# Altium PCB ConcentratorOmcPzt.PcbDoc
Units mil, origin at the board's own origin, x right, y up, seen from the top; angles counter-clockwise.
Board outline 15500 x 6000 mil, 2 copper layers (Top Layer, Bottom Layer); 22 components, 67 nets, 387 pads, 49 vias.
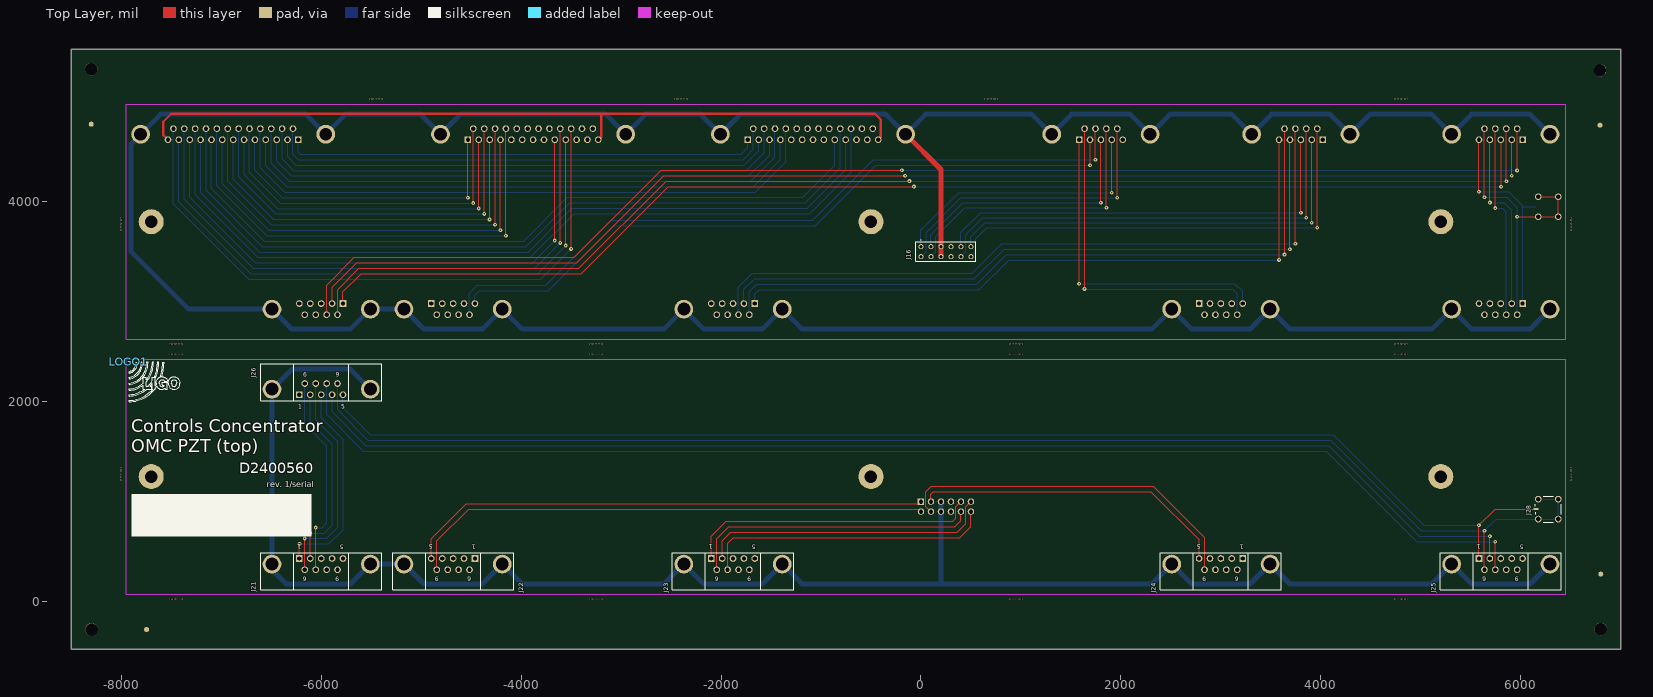
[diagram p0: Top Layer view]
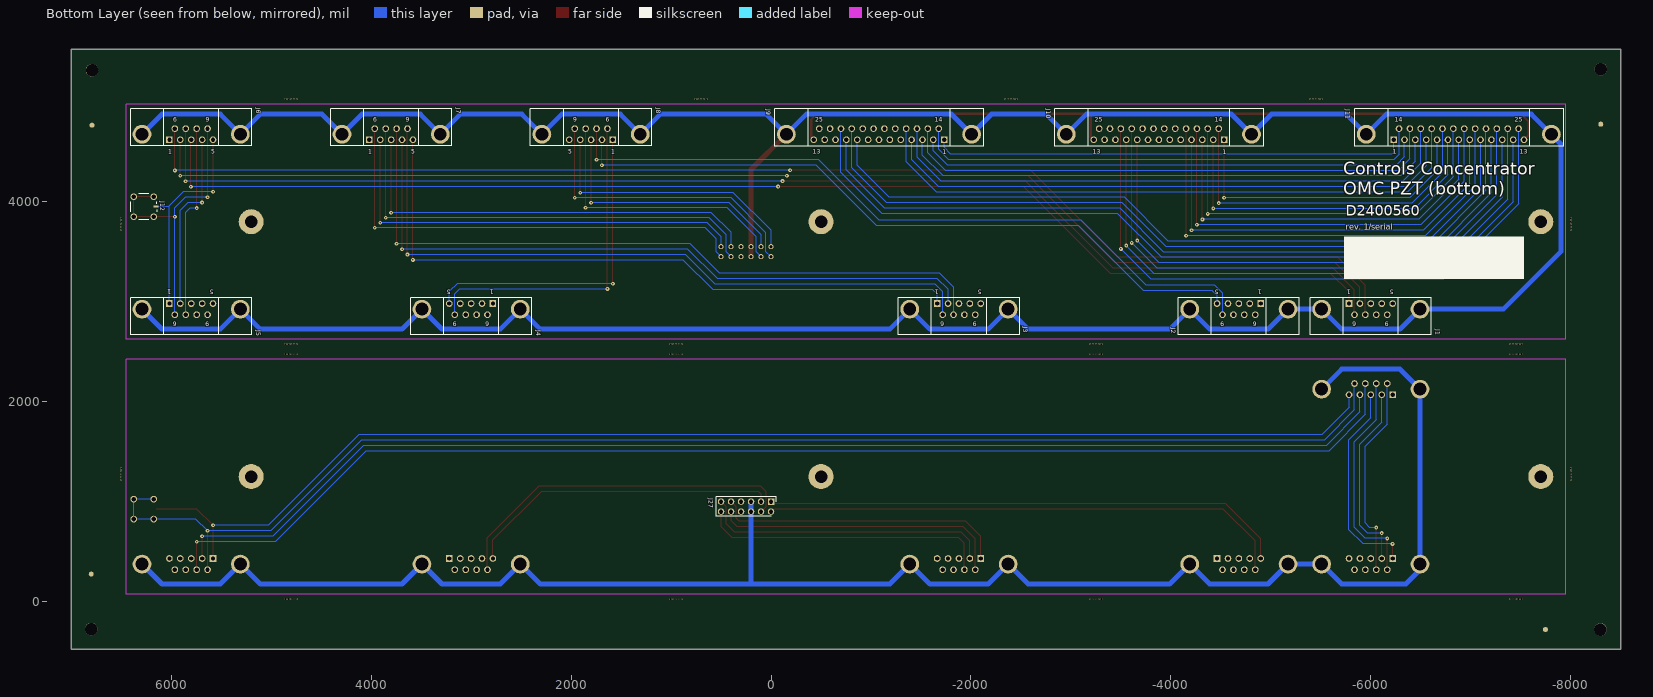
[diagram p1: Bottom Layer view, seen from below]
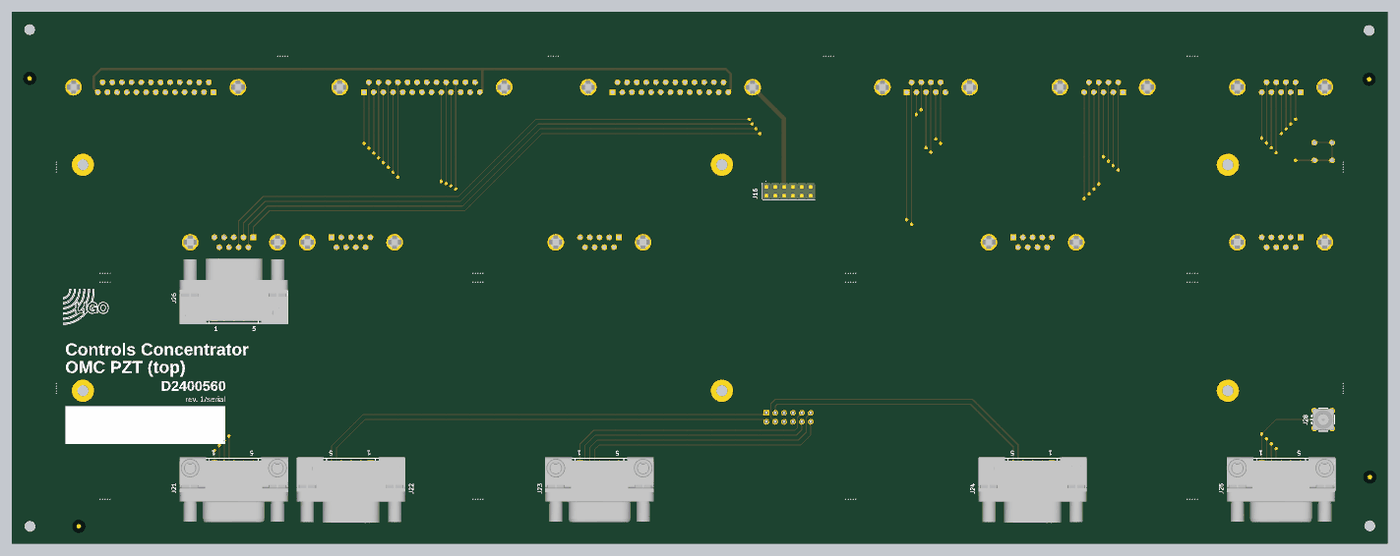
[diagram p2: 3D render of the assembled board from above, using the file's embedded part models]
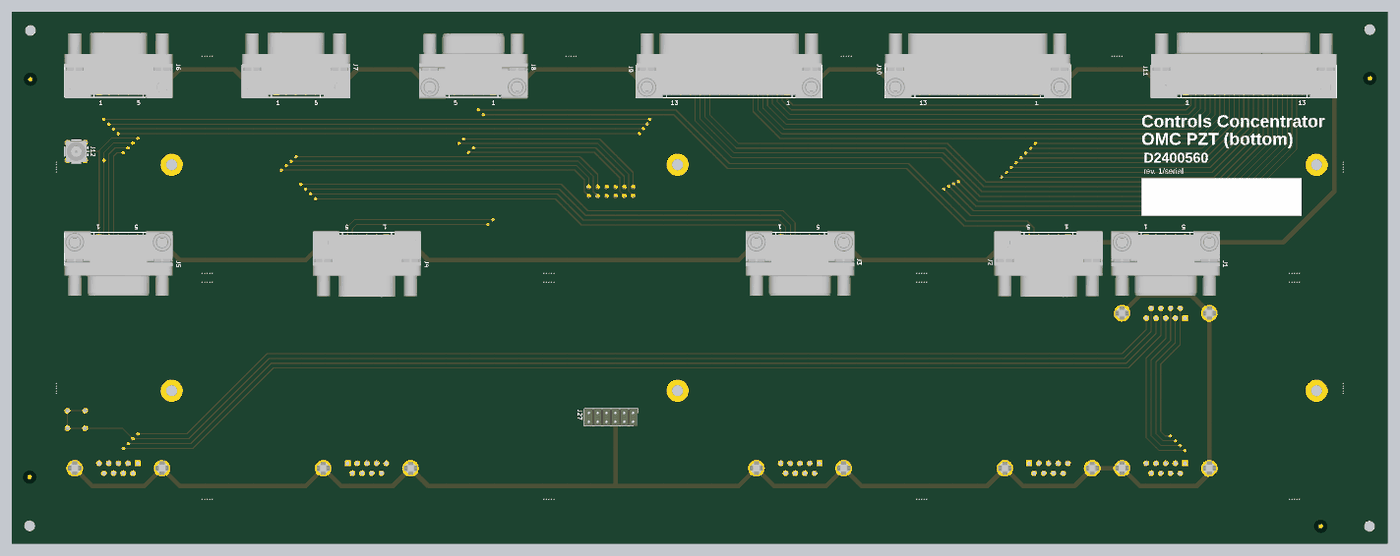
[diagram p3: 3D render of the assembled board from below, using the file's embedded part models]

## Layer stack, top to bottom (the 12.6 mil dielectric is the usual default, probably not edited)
Top Solder: solder mask 0.4, Solder Resist, Dk 3.5
Top Layer: signal copper 1.4
Dielectric1: dielectric 12.6, FR-4, Dk 4.8
Bottom Layer: signal copper 1.4
Bottom Solder: solder mask 0.4, Solder Resist, Dk 3.5

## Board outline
-8500,-475 7000,-475 7000,5525 -8500,5525

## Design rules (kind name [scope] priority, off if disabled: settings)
Clearance [All] p1: gap=12 ignorepadtopadclearanceinfootprint=FALSE
HoleSize [All] p1: absolutevalues=TRUE maxlimit=250 minlimit=15 maxpercent=80.000 minpercent=20.000
MinimumAnnularRing [All] p1: minimumring=10
PolygonConnect [All] p1: connectstyle=Relief reliefconductorwidth=10 reliefentries=4 polygonreliefangle="90 Angle" airgapwidth=10
RoutingTopology [All] p1: topology=Horizontal
RoutingVias [All] p1: holewidth=15 width=38 viastyle="Through Hole" minholewidth=15 minwidth=35 maxholewidth=28 maxwidth=50
SilkToSolderMaskClearance SilkscreenOverComponentPads [IsPad] p1: minsilkscreentomaskgap=6 clearancetoexposedcopper=TRUE
SolderMaskExpansion [All] p1: expansion=4 istentingtop=FALSE
SupplyNets "Schematic Supply Nets_1" [InNet('GNDH')] p1: voltage=0.000
SupplyNets "Schematic Supply Nets" [InNet('GND')] p2: voltage=0.000
Width [All] p1: maxlimit=50 minlimit=12 preferedwidth=12
27 further rules are at their usual default settings.

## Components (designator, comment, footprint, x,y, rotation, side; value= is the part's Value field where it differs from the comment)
J1 "DB9M" DB9M-RA -6000,2925 r0 bottom locked
J2 "DB9F" DB9F-RA -4680,2925 r0 bottom locked
J3 "DB9M" DB9M-RA -1880,2925 r0 bottom locked
J4 "DB9F" DB9F-RA 3000,2925 r0 bottom locked
J5 "DB9M" DB9M-RA 5800,2925 r0 bottom locked
J6 "DB9F" DB9F-RA 5800,4675 r180 bottom locked
J7 "DB9F" DB9F-RA 3800,4675 r180 bottom locked
J8 "DB9M" DB9M-RA 1800,4675 r180 bottom locked
J9 "DB25M" DB25M-RA -1080,4675 r180 bottom locked
J10 "DB25M" DB25M-RA -3880,4675 r180 bottom locked
J11 "DB25F" DB25F-RA -6880,4675 r180 bottom locked
J12 "SMP" SMP 6275,3950 r90 bottom locked
J16 "SLW-106-01-S-D" SLW-106-01-X-D 0,3550 r180 top locked
J21 "DB9M" DB9M-RA -6000,375 r180 top locked
J22 "DB9F" DB9F-RA -4680,375 r180 top locked
J23 "DB9M" DB9M-RA -1880,375 r180 top locked
J24 "DB9F" DB9F-RA 3000,375 r180 top locked
J25 "DB9M" DB9M-RA 5800,375 r180 top locked
J26 "DB9F" DB9F-RA -6000,2125 r0 top locked
J27 "TSW-106-06-G-D" HDRV12W64P254_2X6_1524X495X521P 0,1000 r0 bottom
J28 "SMP" SMP 6275,925 r270 top locked
LOGO1 "LIGO logo" LIGO_LOGO -7925,2400 r0 top

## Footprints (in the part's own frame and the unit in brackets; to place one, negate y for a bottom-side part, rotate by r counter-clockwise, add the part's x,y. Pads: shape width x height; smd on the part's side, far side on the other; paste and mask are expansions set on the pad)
DB9F-RA [mm] "Receptiacle; D Subminiature 9 Position; Right Angle"
  rect 1.69x1.69 hole 1.09: 1(-5.54,-1.42)
  round 1.69 hole 1.09: 2(-2.77,-1.42) 3(0,-1.42) 4(2.77,-1.42) 5(5.54,-1.42) 6(-4.155,1.42) 7(-1.385,1.42) 8(1.385,1.42) 9(4.155,1.42)
  round 4.76 hole 3.26: 10(-12.495,0) 11(12.495,0)
  silkscreen extent -15.4,-2.9 15.4,6.5, body extent -15.49,-3.17 15.49,15.72, height 12.62
DB9M-RA [mm] "Plug; D Subminiature 9 Position; Right Angle"
  rect 1.69x1.69 hole 1.09: 1(5.54,-1.42)
  round 1.69 hole 1.09: 2(2.77,-1.42) 3(0,-1.42) 4(-2.77,-1.42) 5(-5.54,-1.42) 6(4.155,1.42) 7(1.385,1.42) 8(-1.385,1.42) 9(-4.155,1.42)
  round 4.76 hole 3.26: 10(12.495,0) 11(-12.495,0)
  silkscreen extent -15.4,-2.9 15.4,6.5, body extent -15.52,-3.24 15.52,15.37, height 12.62
DB25F-RA [mm] "Receptiacle; D Subminiature 25 Position; Right Angle"
  rect 1.69x1.69 hole 1.09: 1(-16.566,-1.42)
  round 1.69 hole 1.09: 2(-13.805,-1.42) 3(-11.044,-1.42) 4(-8.283,-1.42) 5(-5.522,-1.42) 6(-2.761,-1.42) 7(0,-1.42) 8(2.761,-1.42) 9(5.522,-1.42) 10(8.283,-1.42) 11(11.044,-1.42) 12(13.805,-1.42) 13(16.566,-1.42) 14(-15.185,1.42) 15(-12.425,1.42) 16(-9.663,1.42) 17(-6.903,1.42) 18(-4.142,1.42) 19(-1.38,1.42) 20(1.38,1.42) 21(4.142,1.42) 22(6.903,1.42) 23(9.663,1.42) 24(12.425,1.42) 25(15.185,1.42)
  round 4.76 hole 3.26: 26(-23.526,0) 27(23.526,0)
  silkscreen extent -26.5,-3 26.6,6.5, body extent -26.59,-3.17 26.49,15.72, height 12.62
DB25M-RA [mm] "Plug; D Subminiature 25 Position; Right Angle"
  rect 1.69x1.69 hole 1.09: 1(16.566,-1.42)
  round 1.69 hole 1.09: 2(13.805,-1.42) 3(11.044,-1.42) 4(8.283,-1.42) 5(5.522,-1.42) 6(2.761,-1.42) 7(0,-1.42) 8(-2.761,-1.42) 9(-5.522,-1.42) 10(-8.283,-1.42) 11(-11.044,-1.42) 12(-13.805,-1.42) 13(-16.566,-1.42) 14(15.185,1.42) 15(12.425,1.42) 16(9.663,1.42) 17(6.903,1.42) 18(4.142,1.42) 19(1.38,1.42) 20(-1.38,1.42) 21(-4.142,1.42) 22(-6.903,1.42) 23(-9.663,1.42) 24(-12.425,1.42) 25(-15.185,1.42)
  round 4.76 hole 3.26: 26(23.526,0) 27(-23.526,0)
  silkscreen extent -26.5,-3 26.6,6.5, body extent -26.52,-3.2 26.57,15.4, height 12.62
HDRV12W64P254_2X6_1524X495X521P [mm]
  rect 1.65x1.65 hole 1.1: 1(0,0)
  round 1.65 hole 1.1: 2(0,2.54) 3(2.54,0) 4(2.54,2.54) 5(5.08,0) 6(5.08,2.54) 7(7.62,0) 8(7.62,2.54) 9(10.16,0) 10(10.16,2.54) 11(12.7,0) 12(12.7,2.54)
  silkscreen extent -1.27,-1.2 13.97,3.74, body extent -1.27,-1.2 13.97,3.74, height 5.21
LIGO_LOGO [mil] "LIGO logo"
  silkscreen extent 3,-402 511,-3
SLW-106-01-X-D [mm]
  round 1.3 hole 0.86: 1(0,0) 2(0,2.54) 3(-2.54,0) 4(-2.54,2.54) 5(-5.08,0) 6(-5.08,2.54) 7(-7.62,0) 8(-7.62,2.54) 9(-10.16,0) 10(-10.16,2.54) 11(-12.7,0) 12(-12.7,2.54)
  silkscreen extent -13.97,-1.75 1.27,3.74, body extent -13.97,-1.24 1.27,3.72, height 4.49
SMP [mil] "SMP straight PCB"
  rect 20x50 smd: 1(0,-123)
  round 67 hole 47: 2(-100,-100) 2(-100,100) 2(100,-100) 2(100,100)
  silkscreen extent -130,-130 130,130, body extent -118,-138 118,118, height 161

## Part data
J1 J3 J5 J8 J21 J23 J25: "Plug Assembly, 9 Position, Right Angle, .318 Series", Part Number=571-5747840-4
J2 J4 J6 J7 J22 J24 J26: "Receptacle Assembly, 9 Position, Right Angle, .318 Series", Part Number=571-5747844-4
J9 J10: "Plug Assembly, 25 Position, Right Angle, .318 Series", Part Number=571-5747842-4
J11: "Receptacle Assembly, 25 Position, Right Angle, .318 Series", Part Number=571-5747846-4
J12 J28: "SMP, PCB Mount", Part Number=538-73415-3310
J16: "Connector", Manufacturer_Name=SAMTEC, Mouser Part Number=200-SLW10601SD
J27: "Connector", Manufacturer_Name=SAMTEC, Part Number=200-TSW10606GD
LOGO1: library part LIGO_logo

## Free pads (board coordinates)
  round 50 smd far side paste-50 mask+50: 0(-8300,4775) 0(-7746.62,-279.8) 0(6791.98,4765.13) 0(6800,275)
  round 50 smd paste-50 mask+50: 0(-8300,4775) 0(-7746.62,-279.8) 0(6791.98,4765.13) 0(6800,275)
  round 125 hole 125 unplated: 0(-8300,5325) 0(-8296.62,-279.8) 0(6791.98,5315.13) 0(6800,-275)
  round 18 hole 18 unplated mask+0: 0(-8000,1219) 0(-8000,1247) 0(-8000,1275) 0(-8000,1303) 0(-8000,1331) 0(-8000,3719) 0(-8000,3747) 0(-8000,3775) 0(-8000,3803) 0(-8000,3831) 0(-7506,25) 0(-7506,2475) 0(-7506,2575) 0(-7478,25) 0(-7478,2475) 0(-7478,2575) 0(-7450,25) 0(-7450,2475) 0(-7450,2575) 0(-7422,25) 0(-7422,2475) 0(-7422,2575) 0(-7394,25) 0(-7394,2475) 0(-7394,2575) 0(-5506,5025) 0(-5478,5025) 0(-5450,5025) 0(-5422,5025) 0(-5394,5025) 0(-3306,25) 0(-3306,2475) 0(-3306,2575) 0(-3278,25) 0(-3278,2475) 0(-3278,2575) 0(-3250,25) 0(-3250,2475) 0(-3250,2575) 0(-3222,25) 0(-3222,2475) 0(-3222,2575) 0(-3194,25) 0(-3194,2475) 0(-3194,2575) 0(-2456,5025) 0(-2428,5025) 0(-2400,5025) 0(-2372,5025) 0(-2344,5025) 0(644,5025) 0(672,5025) 0(700,5025) 0(728,5025) 0(756,5025) 0(894,25) 0(894,2475) 0(894,2575) 0(922,25) 0(922,2475) 0(922,2575) 0(950,25) 0(950,2475) 0(950,2575) 0(978,25) 0(978,2475) 0(978,2575) 0(1006,25) 0(1006,2475) 0(1006,2575) 0(4744,25) 0(4744,2475) 0(4744,2575) 0(4744,5025) 0(4772,25) 0(4772,2475) 0(4772,2575) 0(4772,5025) 0(4800,25) 0(4800,2475) 0(4800,2575) 0(4800,5025) 0(4828,25) 0(4828,2475) 0(4828,2575) 0(4828,5025) 0(4856,25) 0(4856,2475) 0(4856,2575) 0(4856,5025) 0(6500,1219) 0(6500,1247) 0(6500,1275) 0(6500,1303) 0(6500,1331) 0(6500,3719) 0(6500,3747) 0(6500,3775) 0(6500,3803) 0(6500,3831)
  round 250 hole 125: 1(-7700,1250) 1(-7700,3800) 1(-500,1250) 1(-500,3800) 1(5200,1250) 1(5200,3800)

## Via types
v1: diameter 38, hole 15, Top Layer to Bottom Layer, 49 vias

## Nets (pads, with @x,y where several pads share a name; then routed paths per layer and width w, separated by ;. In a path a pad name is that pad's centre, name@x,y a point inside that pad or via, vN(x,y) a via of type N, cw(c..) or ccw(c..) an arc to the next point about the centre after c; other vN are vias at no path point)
DownDriveIn1_N: J9.23 J11.23 | length 8272.1
  Bottom Layer w12: J11.23 -7260.45,4067.9 -6634.95,3442.4 -3907.6,3442.4 -3470,3880 -1114.41,3880 -699.55,4294.86 J9.23
DownDriveIn1_P: J9.10 J11.10 | length 8170.1
  Bottom Layer w12: J11.10 -7206.1,4090.42 -6612.44,3496.75 -3930.11,3496.75 -3492.51,3934.35 -1136.92,3934.35 -753.9,4317.38 ; -753.9,4317.38 J9.10 -753.9,4317.38
DownDriveIn2_N: J10.23 J11.25 | length 6371.9
  Top Layer w12: v1(-3500,3527) -3499.55,3527.45 J10.23
  Bottom Layer w12: J11.25 -7477.85,3977.85 -6725,3225 -3802,3225 v1(-3500,3527)
DownDriveIn2_P: J10.10 J11.12 | length 5961.7
  Top Layer w12: v1(-3554,3561) -3553.9,3561.1 J10.10
  Bottom Layer w12: J11.12 -7423.5,4000.37 -6702.49,3279.35 -3835.65,3279.35 v1(-3554,3561)
FaultMon1_N: J9.16 J11.16 | length 5848.4
  Bottom Layer w12: J11.16 -6499.55,4383.08 -6319.77,4203.31 -1700.42,4203.31 -1460.45,4443.27 J9.16
FaultMon1_P: J9.3 J11.3 | length 5444.7
  Bottom Layer w12: J11.3 -6445.2,4405.59 -6297.26,4257.66 -1722.93,4257.66 -1514.8,4465.79 J9.3
FaultMon2_N: J10.16 J11.20 | length 4345.1
  Top Layer w12: v1@-4260.45,3768 J10.16
  Bottom Layer w12: J11.20 -6934.35,4202.98 -6499.87,3768.5 v1@-4260,3768.5
  other v1: -4260,3770
FaultMon2_P: J10.3 J11.7 | length 3921.7
  Top Layer w12: v1(-4314.8,3823) J10.3
  Bottom Layer w12: J11.7 -6880,4225.49 -6477.36,3822.85 v1@-4314.8,3822.85
GND: J1.10 J1.11 J2.10 J2.11 J3.10 J3.11 J4.10 J4.11 J5.10 J5.11 J6.10 J6.11 J7.10 J7.11 J8.10 J8.11 J9.26 J9.27 J10.26 J10.27 J11.26 J11.27 J16.5 J16.6 | length 34262.5
  Top Layer w50: J9.27 200,4321.22 J16.5 J16.6
  Bottom Layer w50: J5.10 6091.93,2725 5508.07,2725 J5.11 5108.07,2725 3691.93,2725 J4.11 3291.93,2725 2708.07,2725 J4.10 2308.07,2725 -1188.07,2725 J3.10 -1588.07,2725 -2171.93,2725 J3.11 -2571.93,2725 -3988.07,2725 J2.11 -4388.07,2725 -4971.93,2725 J2.10 J1.10 -5708.07,2725 -6291.93,2725 J1.11 -7325,2925 -7900,3500 -7900,4577.01 -7806.22,4670.79 J11.27 -7605.19,4876.03 -6154.81,4876.03 J11.26 -5753.78,4875 -5006.22,4875 J10.26 -4606.22,4875 -3153.78,4875 J10.27 -2753.78,4875 -2206.22,4875 J9.26 -1806.22,4875 -353.78,4875 J9.27 46.22,4875 1108.07,4875 J8.10 1508.07,4875 2091.93,4875 J8.11 2491.93,4875 3108.07,4875 J7.11 3508.07,4875 4091.93,4875 J7.10 4491.93,4875 5108.07,4875 J6.11 5508.07,4875 6091.93,4875 J6.10
GNDH: J21.10 J21.11 J22.10 J22.11 J23.10 J23.11 J24.10 J24.11 J25.10 J25.11 J26.10 J26.11 J27.5 J27.6 | length 17867.9
  Bottom Layer w50: J26.11 -5708.07,2325 -6291.93,2325 J26.10 J21.10 -6465.64,348.71 -6465.64,290.64 -6350,175 -5708.07,175 J21.11 J22.11 -4971.93,175 -4388.07,175 J22.10 -3988.07,175 -2571.93,175 J23.10 -2171.93,175 -1588.07,175 J23.11 -1188.07,175 200,175 ; J27.5 J27.6 200,175 ; J25.11 6091.93,175 5508.07,175 J25.10 5108.07,175 3691.93,175 J24.10 3291.93,175 2708.07,175 J24.11 2308.07,175 200,175
HiBiasAC_N: J23.7 J27.12 | length 2919.1
  Top Layer w12: J23.7 -1934.53,585.47 -1880,640 390,640 500,750 J27.12
HiBiasAC_P: J23.2 J27.11 | length 2958.1
  Top Layer w12: J23.2 -1989.06,608.06 -1902.59,694.53 364.53,694.53 450,780 450,950 ; 450,920 450,950 ; J27.11 450,950
HiBiasDC_N: J23.6 J27.10 | length 2919.4
  Top Layer w12: J23.6 -2043.58,630.64 -1925.17,749.05 339.05,749.05 400,810 J27.10
HiBiasDC_P: J23.1 J27.9 | length 2932.3
  Top Layer w12: J23.1 -2098.11,653.23 -1947.76,803.58 320,803.58 350,833.58 350,950 J27.9
HiHvAC_N: J21.7 J26.6 | length 2035.9
  Top Layer w12: J21.7 v1(-6054.53,740)
  Bottom Layer w12: J26.6 -6163.58,1772.24 -5943.58,1552.24 -5943.58,787.76 -5991.34,740 v1(-6054.53,740)
HiHvAC_P: J21.2 J26.2 | length 1902.4
  Top Layer w12: J21.2 v1(-6109.06,685)
  Bottom Layer w12: v1(-6109.06,685) -6108.58,685.47 -5968.75,685.47 -5889.05,765.17 -5889.05,1574.83 -6109.05,1794.83 J26.2
HiHvDC_N: J21.6 J26.7 | length 2216.6
  Top Layer w12: J21.6 v1(-6163.58,631)
  Bottom Layer w12: v1@-6163.58,630.95 -5946.17,630.95 -5834.53,742.59 -5834.53,1597.41 -6054.53,1817.41 J26.7
HiHvDC_P: J21.1 J26.3 | length 2083.1
  Top Layer w12: J21.1 v1(-6218.11,576)
  Bottom Layer w12: v1(-6218.11,576) -6217.69,576.42 -5923.58,576.42 -5780,720 -5780,1620 -6000,1840 J26.3
HiHvDrive_N: J22.9 J27.2 | length 5273.2
  Top Layer w12: J22.9 -4843.58,606.42 -4525,925 -75,925 -33.03,925 -8.03,900 J27.2
HiHvDrive_P: J22.5 J27.1 | length 5249.9
  Top Layer w12: J22.5 -4898.11,629 -4547.59,979.53 -75,979.53 -20.47,979.53 J27.1
HiLoBiasAC_N: J7.6 J16.12 | length 4650.8
  Top Layer w12: v1(3963.58,3740) J7.6
  Bottom Layer w12: J16.12 550.25,3500.25 550.25,3630.25 660,3740 v1(3963.58,3740)
HiLoBiasAC_P: J7.2 J16.11 | length 4397
  Top Layer w12: v1(3909.05,3790) J7.2
  Bottom Layer w12: J16.11 500,3651.07 639.18,3790.25 3908.8,3790.25 v1(3909.05,3790)
HiLoBiasDC_N: J7.7 J16.10 | length 4607.4
  Top Layer w12: v1(3854.53,3840) J7.7
  Bottom Layer w12: J16.10 450.25,3500.25 450.25,3671.68 618.58,3840 v1(3854.53,3840)
HiLoBiasDC_P: J7.3 J16.9 | length 4353.5
  Top Layer w12: v1(3800,3890) J7.3
  Bottom Layer w12: J16.9 400,3692.49 597.76,3890.25 v1@3800,3890.25
HiLoHvDrive_N: J8.9 J16.2 | length 3011
  Top Layer w12: v1(1963.58,4040) J8.9
  Bottom Layer w12: J16.2 50.25,3500.25 50.25,3691.68 398.58,4040 v1(1963.58,4040)
HiLoHvDrive_P: J8.4 J16.1 | length 2757.2
  Top Layer w12: v1(1909.05,4090) J8.4
  Bottom Layer w12: J16.1 0,3712.49 377.76,4090.25 1908.8,4090.25 v1(1909.05,4090)
HiLoLvDrive_N: J8.8 J16.4 | length 2836.3
  Top Layer w12: v1(1854.53,3940) J8.8
  Bottom Layer w12: J16.4 150.25,3500.25 150.25,3650.25 440,3940 v1(1854.53,3940)
HiLoLvDrive_P: J8.3 J16.3 | length 2582.4
  Top Layer w12: v1(1800,3990) J8.3
  Bottom Layer w12: J16.3 100,3671.07 419.18,3990.25 v1@1800,3990.25
HiLvAC_N: J25.7 J26.8 | length 12804.7
  Top Layer w12: J25.7@5745,319.57 v1(5745,599.21)
  Bottom Layer w12: J26.8 -5945.47,1874.13 -5577.29,1505.95 4054.05,1505.95 4960,600 v1@5745,600
HiLvAC_P: J25.2 J26.4 | length 12491.9
  Top Layer w12: J25.2 v1(5690.94,654)
  Bottom Layer w12: J26.4 -5890.94,1896.72 -5554.7,1560.48 4076.64,1560.48 4982.59,654.53 v1@5690.94,654.53
HiLvDC_N: J25.6 J26.9 J28.2 | length 13812
  Top Layer w12: J25.6 v1(5636.42,708.58)
  Bottom Layer w12: J26.9 -5836.42,1919.3 -5532.12,1615 4099.22,1615 5005.17,709.05 v1@5636.42,709.05 ; v1(5636.42,708.58) 5752.84,825 6175,825 6375,825 6375,1025 J28.2@6175,1025
HiLvDC_P: J25.1 J26.5 J28.1 | length 12946.4
  Top Layer w12: J25.1 v1(5581.89,763) 5743.89,925 J28.1@6150,925
  Bottom Layer w12: J26.5 -5781.89,1941.89 -5509.53,1669.53 4121.81,1669.53 5027.76,763.58 v1@5581.89,763.58
HiLvDrive_N: J24.9 J27.4 | length 3564.2
  Top Layer w12: J27.4 50,950 50,1100 104.53,1154.53 2322.59,1154.53 2836.42,640.7 J24.9
HiLvDrive_P: J24.5 J27.3 | length 3154.1
  Top Layer w12: J27.3 100,1075 125,1100 2300,1100 2781.89,618.11 J24.5
HVReadyMon1_N: J9.14 J11.14 | length 5134.6
  Bottom Layer w12: J11.14 -6282.15,4473.13 -6229.72,4420.71 -1779.29,4420.71 -1677.85,4522.15 J9.14
HVReadyMon1_P: J9.1 J11.1 | length 4731.9
  Bottom Layer w12: J11.1 -6227.8,4495.65 -6207.21,4475.06 -1799.94,4475.06 -1732.2,4542.8 J9.1
HVReadyMon2_N: J10.14 J11.18 | length 3549.1
  Top Layer w12: v1(-4477.85,3986) J10.14
  Bottom Layer w12: J11.18 -6716.95,4293.03 -6409.82,3985.91 v1@-4477.85,3985.91
HVReadyMon2_P: J10.1 J11.5 | length 3127.1
  Top Layer w12: v1(-4532.2,4040) J10.1
  Bottom Layer w12: J11.5 -6662.6,4315.54 -6387.31,4040.26 v1@-4532.2,4040.26
LoBiasAC_N: J3.7 J7.8 | length 7178.4
  Top Layer w12: v1(3745.47,3580) J7.8
  Bottom Layer w12: J3.7 -1825.47,3145.87 -1687.76,3283.58 512.24,3283.58 808.66,3580 v1(3745.47,3580)
LoBiasAC_P: J3.2 J7.4 | length 6865
  Top Layer w12: v1(3690.94,3525) J7.4
  Bottom Layer w12: J3.2 -1770.94,3123.28 -1665.17,3229.05 534.83,3229.05 831.25,3525.47 v1@3690.94,3525.47
LoBiasDC_N: J3.6 J7.9 | length 6997.7
  Top Layer w12: v1(3636.42,3471) J7.9
  Bottom Layer w12: J3.6 -1716.42,3100.7 -1642.59,3174.53 557.41,3174.53 853.83,3470.95 v1@3636.42,3470.95
LoBiasDC_P: J3.1 J7.5 | length 6683.5
  Top Layer w12: v1(3581.89,3417) J7.5
  Bottom Layer w12: J3.1 -1661.89,3078.11 -1620,3120 580,3120 876.42,3416.42 3581.31,3416.42 v1(3581.89,3417)
LoHvAC_N: J1.7 J6.6 | length 13099.1
  Top Layer w12: J1.7 -5945.47,3165.87 -5667.76,3443.58 -3467.76,3443.58 -2597.76,4313.58 v1(-190,4313.58) ; v1(5963.58,4313) J6.6
  Bottom Layer w12: v1(-190,4313.58) v1@5963.58,4313.58
LoHvAC_P: J1.2 J6.2 | length 12785.4
  Top Layer w12: J1.2 -5890.94,3143.28 -5645.17,3389.05 -3445.17,3389.05 -2574.23,4260 v1(-159,4260) ; v1(5909.05,4259) J6.2
  Bottom Layer w12: v1(-159,4260) -158.05,4259.05 v1@5909.05,4259.05
LoHvDC_N: J1.6 J6.7 | length 12924.2
  Top Layer w12: J1.6 -5836.42,3120.7 -5622.59,3334.53 -3422.59,3334.53 -2550.11,4207 v1(-115,4207) ; J6.7 5857,4728.43 v1(5857,4204)
  Bottom Layer w12: v1(-115,4207) 5854,4207 v1(5857,4204)
LoHvDC_P: J1.1 J6.3 | length 12608.2
  Top Layer w12: J1.1 -5781.89,3098.11 -5600,3280 -3400,3280 -2529,4151 v1(-71,4151) ; J6.3 5802.47,4616.62 v1(5802.47,4150)
  Bottom Layer w12: v1(-71,4151) 5801.47,4151 v1(5802.47,4150)
LoHvDrive_N: J2.9 J8.7 | length 7342.1
  Top Layer w12: v1(1745.47,4420) J8.7
  Bottom Layer w12: J2.9 -4516.42,3085.7 -4437.59,3164.53 -3752.59,3164.53 -3102.59,3814.53 -1082.59,3814.53 -477.11,4420 v1(1745.47,4420)
LoHvDrive_P: J2.5 J8.2 | length 7028.7
  Top Layer w12: v1(1690.94,4365.06) J8.2
  Bottom Layer w12: J2.5 -4461.89,3063.11 -4415,3110 -3730,3110 -3080,3760 -1060,3760 -454.53,4365.47 1690.53,4365.47 v1(1690.94,4365.06)
LoLvAC_N: J5.7 J6.8 | length 1946.7
  Top Layer w12: v1(5745.47,3936) J6.8
  Bottom Layer w12: v1(5745.47,3936) 5745.89,3936.42 5812.24,3936.42 5854.53,3894.13 J5.7
LoLvAC_P: J5.2 J6.4 | length 1812.8
  Top Layer w12: v1(5690.94,3991) J6.4
  Bottom Layer w12: v1(5690.94,3991) 5691,3990.95 5834.83,3990.95 5909.06,3916.72 J5.2
LoLvDC_N: J5.6 J6.9 J12.2 | length 2939.3
  Top Layer w12: v1(5636.42,4045) J6.9 ; v1(5963,3850) 6175,3850 6375,3850 6375,4050 J12.2@6175,4050
  Bottom Layer w12: v1@5636.42,4045.47 5857.41,4045.47 5963.58,3939.3 J5.6
LoLvDC_P: J5.1 J6.5 J12.1 | length 2127.8
  Top Layer w12: v1(5581.89,4100) J6.5
  Bottom Layer w12: v1(5581.89,4100) 5880,4100 6018.11,3961.89 6018.11,3949 ; J5.1 6018.11,3949 ; J12.1 6019.11,3950 6018.11,3949
LoLvDrive_N: J4.9 J8.6 | length 3362.5
  Top Layer w12: v1@1636.42,3125 J8.6
  Bottom Layer w12: v1(1637,3127) 1638.53,3125.47 3117.41,3125.47 3163.58,3079.3 J4.9
LoLvDrive_P: J4.5 J8.1 | length 3228.7
  Top Layer w12: v1(1581.89,3180) J8.1
  Bottom Layer w12: v1(1581.89,3180) 3140,3180 3218.11,3101.89 J4.5
RGDN: J9.13 J10.13 J11.13 | length 7923.5
  Top Layer w25: J11.13 -7580,4666.89 -7580,4800 -7500,4880 -460,4880 -400,4820 -400,4646.89 J9.13 ; J10.13 -3200,4646.89 -3200,4880
SpareMon1_N: J9.17 J11.17 | length 6208.6
  Bottom Layer w12: J11.17 -6608.25,4338.06 -6364.8,4094.61 -1655.39,4094.61 -1351.75,4398.25 J9.17
SpareMon1_P: J9.4 J11.4 | length 5804.9
  Bottom Layer w12: J11.4 -6553.9,4360.57 -6342.28,4148.96 -1677.91,4148.96 -1406.1,4420.76 J9.4
SpareMon2_N: J10.17 J11.21 | length 4741.5
  Top Layer w12: v1(-4151.75,3660) J10.17
  Bottom Layer w12: J11.21 -7043.05,4157.95 -6544.9,3659.8 v1@-4151.75,3659.8
SpareMon2_P: J10.4 J11.8 | length 4319.5
  Top Layer w12: v1(-4206.1,3714) J10.4
  Bottom Layer w12: J11.8 -6988.7,4180.47 -6522.39,3714.15 v1@-4206.1,3714.15
StatusMon1_N: J9.15 J11.15 | length 5488.2
  Bottom Layer w12: J11.15 -6390.85,4428.11 -6274.75,4312.01 -1745.45,4312.01 -1569.15,4488.3 J9.15
StatusMon1_P: J9.2 J11.2 | length 5084.5
  Bottom Layer w12: J11.2 -6336.5,4450.62 -6252.23,4366.36 -1767.96,4366.36 -1623.5,4510.81 J9.2
StatusMon2_N: J10.15 J11.19 | length 3946.9
  Top Layer w12: v1(-4369.15,3877) J10.15
  Bottom Layer w12: J11.19 -6825.65,4248.01 -6454.85,3877.2 v1@-4369.15,3877.2
StatusMon2_P: J10.2 J11.6 | length 3523.9
  Top Layer w12: v1(-4423.5,3932) J10.2
  Bottom Layer w12: J11.6 -6771.3,4270.52 -6432.34,3931.55 v1@-4423.5,3931.55
UpDriveIn1_N: J9.22 J11.22 | length 8303
  Bottom Layer w12: J11.22 -7151.75,4112.93 -6589.92,3551.1 -3952.62,3551.1 -3515.02,3988.7 -1159.44,3988.7 -808.25,4339.89 ; -808.25,4339.89 J9.22 -808.25,4339.89
UpDriveIn1_P: J9.9 J11.9 | length 7764.9
  Bottom Layer w12: J11.9 -7097.4,4135.44 -6567.41,3605.45 -3975.14,3605.45 -3537.54,4043.05 -1181.95,4043.05 -862.6,4362.4 ; -862.6,4362.4 J9.9 -862.6,4362.4
UpDriveIn2_N: J10.22 J11.24 | length 6002.8
  Top Layer w12: v1(-3609,3587) -3608.25,3587.75 J10.22
  Bottom Layer w12: J11.24 -7369.15,4022.88 -6679.98,3333.7 -3862.3,3333.7 v1(-3609,3587)
UpDriveIn2_P: J10.9 J11.11 | length 5598.4
  Top Layer w12: v1(-3663,3611) -3662.6,3611.4 J10.9
  Bottom Layer w12: J11.11 -7314.8,4045.39 -6657.46,3388.05 -3885.95,3388.05 v1(-3663,3611)
pads on no net: J1.3 J1.4 J1.5 J1.8 J1.9 J2.1 J2.2 J2.3 J2.4 J2.6 J2.7 J2.8 J3.3 J3.4 J3.5 J3.8 J3.9 J4.1 J4.2 J4.3 J4.4 J4.6 J4.7 J4.8 J5.3 J5.4 J5.5 J5.8 J5.9 J6.1 J7.1 J8.5 J9.5 J9.6 J9.7 J9.8 J9.11 J9.12 J9.18 J9.19 J9.20 J9.21 J9.24 J9.25 J10.5 J10.6 J10.7 J10.8 J10.11 J10.12 J10.18 J10.19 J10.20 J10.21 J10.24 J10.25 J16.7 J16.8 J21.3 J21.4 J21.5 J21.8 J21.9 J22.1 J22.2 J22.3 J22.4 J22.6 J22.7 J22.8 J23.3 J23.4 J23.5 J23.8 J23.9 J24.1 J24.2 J24.3 J24.4 J24.6 J24.7 J24.8 J25.3 J25.4 J25.5 J25.8 J25.9 J26.1 J27.7 J27.8

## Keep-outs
Keep-Out Layer:
  lines w10: -7950,75 6450,75 6450,2425 -7950,2425 -7950,75 ; -7950,2625 -7950,4975 6450,4975 6450,2625 -7950,2625

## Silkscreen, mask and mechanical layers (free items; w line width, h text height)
Top Overlay:
  rectangle: -7895,650 -6095,1075
  text "Controls Concentrator" at -7900,1650 h220
  text "OMC PZT (top)" at -7900,1450 h220
  text "D2400560" at -6820,1250 h180
  text "rev. 1/serial" at -6545,1125 h100
Bottom Overlay:
  region: -5730,3650 -7530,3650 -7530,3225 -5730,3225
  text "Controls Concentrator" at -5725,4225 h220
  text "OMC PZT (bottom)" at -5725,4025 h220
  text "D2400560" at -5750,3825 h180
  text "rev. 1/serial" at -5750,3700 h100
Mechanical 1:
  lines w10: -8500,-475 -8500,5525 7000,5525 7000,-475 -8500,-475 ; -8100,-75 -7550,-75 ccw(c-7550,-25) -7550,25 -8000,25 -8000,1175 ccw(c-8050,1175) -8100,1175 -8100,-75 ; -8100,1375 ccw(c-8050,1375) -8000,1375 -8000,2475 -7550,2475 ccw(c-7550,2525) -7550,2575 -8000,2575 -8000,3675 ccw(c-8050,3675) -8100,3675 -8100,1375 ; -8100,3875 ccw(c-8050,3875) -8000,3875 -8000,5025 -5550,5025 ccw(c-5550,5075) -5550,5125 -8100,5125 -8100,3875 ; -7350,-75 cw(c-7350,-25) -7350,25 -3350,25 cw(c-3350,-25) -3350,-75 -7350,-75 ; -7350,2475 cw(c-7350,2525) -7350,2575 -3350,2575 cw(c-3350,2525) -3350,2475 -7350,2475 ; -5350,5025 cw(c-5350,5075) -5350,5125 -2500,5125 cw(c-2500,5075) -2500,5025 -5350,5025 ; -3150,-75 cw(c-3150,-25) -3150,25 850,25 cw(c850,-25) 850,-75 -3150,-75 ; -3150,2475 cw(c-3150,2525) -3150,2575 850,2575 cw(c850,2525) 850,2475 -3150,2475 ; -2300,5025 cw(c-2300,5075) -2300,5125 600,5125 cw(c600,5075) 600,5025 -2300,5025 ; 800,5025 cw(c800,5075) 800,5125 4700,5125 cw(c4700,5075) 4700,5025 800,5025 ; 1050,-75 cw(c1050,-25) 1050,25 4700,25 cw(c4700,-25) 4700,-75 1050,-75 ; 1050,2475 cw(c1050,2525) 1050,2575 4700,2575 cw(c4700,2525) 4700,2475 1050,2475 ; 4900,-75 cw(c4900,-25) 4900,25 6500,25 6500,1175 cw(c6550,1175) 6600,1175 6600,-75 4900,-75 ; 4900,2475 cw(c4900,2525) 4900,2575 6500,2575 6500,3675 cw(c6550,3675) 6600,3675 6600,1375 cw(c6550,1375) 6500,1375 6500,2475 4900,2475 ; 4900,5025 cw(c4900,5075) 4900,5125 6600,5125 6600,3875 cw(c6550,3875) 6500,3875 6500,5025 4900,5025
Mechanical 2:
  lines w10: -8000,25 6500,25 6500,2475 -8000,2475 -8000,25 ; -8000,2575 6500,2575 6500,5025 -8000,5025 -8000,2575
Drill Drawing:
  circle w10: c-8329.31,5833.33 r33.33
  lines w10: -8362.65,5950 -8295.98,5950 -8295.98,6016.67 -8362.65,6016.67 -8362.65,5950 ; -8362.65,6116.67 -8345.98,6116.67 -8345.98,6100 -8312.65,6100 -8312.65,6116.67 -8295.98,6116.67 -8295.98,6150 -8312.65,6150 -8312.65,6166.67 -8345.98,6166.67 -8345.98,6150 -8362.65,6150 -8362.65,6116.67 ; -8362.65,6250 -8295.98,6250 -8295.98,6316.67 -8362.65,6316.67 -8362.65,6250 ; -8362.65,6416.67 -8345.98,6416.67 -8329.31,6400 -8312.65,6416.67 -8295.98,6416.67 -8312.65,6433.33 -8295.98,6450 -8312.65,6450 -8329.31,6466.67 -8345.98,6450 -8362.65,6450 -8345.98,6433.33 -8362.65,6416.67 ; -8362.65,6616.67 -8295.98,6616.67 -8329.31,6550 -8362.65,6616.67 ; -8362.65,6700 -8362.65,6716.67 -8345.98,6733.33 -8362.65,6750 -8362.65,6766.67 -8345.98,6766.67 -8329.31,6750 -8312.65,6766.67 -8295.98,6766.67 -8295.98,6750 -8312.65,6733.33 -8295.98,6716.67 -8295.98,6700 -8312.65,6700 -8329.31,6716.67 -8345.98,6700 -8362.65,6700 ; -8362.65,6883.33 -8329.31,6850 -8295.98,6883.33 -8329.31,6916.67 -8362.65,6883.33 ; -8362.65,7000 -8329.31,7016.67 -8295.98,7000 -8312.65,7033.33 -8295.98,7066.67 -8329.31,7050 -8362.65,7066.67 -8345.98,7033.33 -8362.65,7000 ; -8349.31,5963.33 -8309.31,5963.33 -8309.31,6003.33 -8349.31,6003.33 -8349.31,5963.33
  lines w15: -8422.44,5755 2208.61,5755 ; -8422.44,7105 2208.61,7105 ; -7871.56,5605 -7871.56,7255 ; -7271.72,5605 -7271.72,7255 ; -6122.06,5605 -6122.06,7255 ; -5616.18,5605 -5616.18,7255 ; -4882.38,5605 -4882.38,7255 ; -3382.83,5605 -3382.83,7255 ; -2792.98,5605 -2792.98,7255 ; -2047.18,5605 -2047.18,7255 ; -1357.37,5605 -1357.37,7255 ; -503.61,5605 -503.61,7255 ; 830,5605 830,7255 ; -8422.44,5605 2208.61,5605 2208.61,7255 -8422.44,7255 -8422.44,5605
  text "Symbol" at -8332.44,7150 h72
  text "Count" at -7826.56,7150 h72
  text "Hole Size" at -7226.72,7150 h72
  text "Plated" at -6077.06,7150 h72
  text "Hole Type" at -5571.18,7150 h72
  text "Drill Layer Pair" at -4837.38,7150 h72
  text "Via/Pad" at -3337.83,7150 h72
  text "Pad Shape" at -2747.98,7150 h72
  text "Template" at -2002.18,7150 h72
  text "Description" at -1312.37,7150 h72
  text "Hole Tolerance (+)" at -458.61,7150 h72
  text "Hole Tolerance (-)" at 875,7150 h72
  text "4" at -7826.56,7000 h60
  text "125.00mil (3.175mm)" at -7226.72,7000 h60
  text "NPTH" at -6077.06,7000 h60
  text "Round" at -5571.18,7000 h60
  text "Top Layer - Bottom Layer" at -4837.38,7000 h60
  text "Pad" at -3337.83,7000 h60
  text "Rounded" at -2747.98,7000 h60
  text "c318hn318" at -2002.18,7000 h60
  text "6" at -7826.56,6850 h60
  text "125.00mil (3.175mm)" at -7226.72,6850 h60
  text "PTH" at -6077.06,6850 h60
  text "Round" at -5571.18,6850 h60
  text "Top Layer - Bottom Layer" at -4837.38,6850 h60
  text "Pad" at -3337.83,6850 h60
  text "Rounded" at -2747.98,6850 h60
  text "c635h318" at -2002.18,6850 h60
  text "8" at -7826.56,6700 h60
  text "47.00mil (1.194mm)" at -7226.72,6700 h60
  text "PTH" at -6077.06,6700 h60
  text "Round" at -5571.18,6700 h60
  text "Top Layer - Bottom Layer" at -4837.38,6700 h60
  text "Pad" at -3337.83,6700 h60
  text "Rounded" at -2747.98,6700 h60
  text "c170h119" at -2002.18,6700 h60
  text "12" at -7826.56,6550 h60
  text "33.86mil (0.860mm)" at -7226.72,6550 h60
  text "PTH" at -6077.06,6550 h60
  text "Round" at -5571.18,6550 h60
  text "Top Layer - Bottom Layer" at -4837.38,6550 h60
  text "Pad" at -3337.83,6550 h60
  text "Rounded" at -2747.98,6550 h60
  text "c130h86" at -2002.18,6550 h60
  text "12" at -7826.56,6400 h60
  text "43.31mil (1.100mm)" at -7226.72,6400 h60
  text "PTH" at -6077.06,6400 h60
  text "Round" at -5571.18,6400 h60
  text "Top Layer - Bottom Layer" at -4837.38,6400 h60
  text "Pad" at -3337.83,6400 h60
  text "(Mixed)" at -2747.98,6400 h60
  text "(Mixed)" at -2002.18,6400 h60
  text "34" at -7826.56,6250 h60
  text "128.35mil (3.260mm)" at -7226.72,6250 h60
  text "PTH" at -6077.06,6250 h60
  text "Round" at -5571.18,6250 h60
  text "Top Layer - Bottom Layer" at -4837.38,6250 h60
  text "Pad" at -3337.83,6250 h60
  text "Rounded" at -2747.98,6250 h60
  text "c476h326" at -2002.18,6250 h60
  text "49" at -7826.56,6100 h60
  text "15.00mil (0.381mm)" at -7226.72,6100 h60
  text "PTH" at -6077.06,6100 h60
  text "Round" at -5571.18,6100 h60
  text "Top Layer - Bottom Layer" at -4837.38,6100 h60
  text "Via" at -3337.83,6100 h60
  text "Rounded" at -2747.98,6100 h60
  text "v97h38" at -2002.18,6100 h60
  text "100" at -7826.56,5950 h60
  text "18.00mil (0.457mm)" at -7226.72,5950 h60
  text "NPTH" at -6077.06,5950 h60
  text "Round" at -5571.18,5950 h60
  text "Top Layer - Bottom Layer" at -4837.38,5950 h60
  text "Pad" at -3337.83,5950 h60
  text "Rounded" at -2747.98,5950 h60
  text "c46hn46m46" at -2002.18,5950 h60
  text "201" at -7826.56,5800 h60
  text "42.91mil (1.090mm)" at -7226.72,5800 h60
  text "PTH" at -6077.06,5800 h60
  text "Round" at -5571.18,5800 h60
  text "Top Layer - Bottom Layer" at -4837.38,5800 h60
  text "Pad" at -3337.83,5800 h60
  text "(Mixed)" at -2747.98,5800 h60
  text "(Mixed)" at -2002.18,5800 h60
  text "426 Total" at -7826.56,5650 h60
